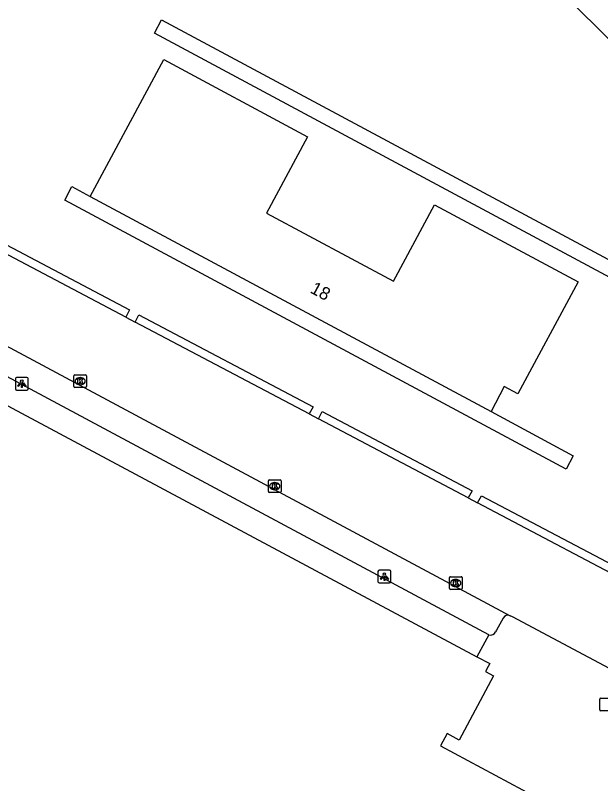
# Model space of a CAD drawing. Extents: x 159489 to 160304, y 383826 to 384530.
# Drawn here: x 160037.7 to 160083.4, y 384048.7 to 384108.8 of the extents above; entities that cross this region are included whole.
import ezdxf

# ---------------------------------------------------------------- set-up
doc = ezdxf.new("R2010")
doc.units = 0
for name, color, linetype in [('IMGEO_Haag', 7, 'Continuous'), ('IMGEO_Kolk', 7, 'Continuous'), ('IMGEO_Lichtpunt', 7, 'Continuous'), ('IMGEO_Muur', 7, 'Continuous'), ('IMGEO_Pand', 7, 'Continuous'), ('IMGEO_Pand_nummerreeks', 7, 'Continuous'), ('IMGEO_Rijbaan_lokaal_open', 7, 'Continuous'), ('IMGEO_Rioolput', 7, 'Continuous'), ('IMGEO_Voetpad_open', 7, 'Continuous')]:
    doc.layers.add(name, color=color, linetype=linetype)

msp = doc.modelspace()

# ---------------------------------------------------------------- linework, layer by layer
at = {"layer": 'IMGEO_Haag'}
for points in [[(160033.002, 384092.187), (160033.287, 384092.784), (160046.606, 384085.746), (160046.301, 384085.17)], [(160047.03, 384084.787), (160047.334, 384085.363), (160060.949, 384078.169), (160060.648, 384077.604)], [(160061.378, 384077.213), (160061.675, 384077.787), (160073.388, 384071.599), (160073.089, 384071.038)], [(160073.826, 384070.649), (160074.121, 384071.211), (160087.845, 384063.961), (160087.565, 384063.401)]]:
    msp.add_lwpolyline(points, dxfattribs=at)
at = {"layer": 'IMGEO_Kolk'}
for p, q in [((160042.238, 384079.744), (160042.238, 384080.596)), ((160042.313, 384080.67), (160043.165, 384080.67)), ((160042.726, 384080.45), (160042.751, 384080.45)), ((160043.239, 384080.596), (160043.239, 384079.744)), ((160043.165, 384079.67), (160042.313, 384079.67)), ((160042.749, 384079.89), (160042.724, 384079.89)), ((160057.457, 384071.53), (160057.457, 384072.382)), ((160057.532, 384072.456), (160058.384, 384072.456)), ((160058.458, 384072.382), (160058.458, 384071.53)), ((160057.945, 384072.236), (160057.97, 384072.236)), ((160058.384, 384071.456), (160057.532, 384071.456)), ((160057.968, 384071.676), (160057.943, 384071.676)), ((160071.614, 384063.944), (160071.614, 384064.796)), ((160071.689, 384064.87), (160072.541, 384064.87)), ((160072.102, 384064.65), (160072.127, 384064.65)), ((160072.615, 384064.796), (160072.615, 384063.944)), ((160072.125, 384064.09), (160072.1, 384064.09)), ((160072.541, 384063.87), (160071.689, 384063.87))]:
    msp.add_line(p, q, dxfattribs=at)
for points in [[(160042.238, 384079.744), (160042.238, 384080.596)], [(160042.313, 384080.67), (160043.165, 384080.67)], [(160042.559, 384080.37), (160042.682, 384080.37), (160042.682, 384080.219), (160042.812, 384080.37), (160042.976, 384080.37), (160042.83, 384080.219), (160042.983, 384079.97), (160042.831, 384079.97), (160042.746, 384080.134), (160042.682, 384080.067), (160042.682, 384079.97), (160042.559, 384079.97), (160042.559, 384080.37)], [(160043.239, 384080.596), (160043.239, 384079.744)], [(160043.165, 384079.67), (160042.313, 384079.67)], [(160057.457, 384071.53), (160057.457, 384072.382)], [(160057.532, 384072.456), (160058.384, 384072.456)], [(160058.458, 384072.382), (160058.458, 384071.53)], [(160057.778, 384072.156), (160057.901, 384072.156), (160057.901, 384072.005), (160058.031, 384072.156), (160058.195, 384072.156), (160058.049, 384072.005), (160058.202, 384071.756), (160058.05, 384071.756), (160057.965, 384071.92), (160057.901, 384071.853), (160057.901, 384071.756), (160057.778, 384071.756), (160057.778, 384072.156)], [(160058.384, 384071.456), (160057.532, 384071.456)], [(160071.614, 384063.944), (160071.614, 384064.796)], [(160071.689, 384064.87), (160072.541, 384064.87)], [(160071.935, 384064.57), (160072.058, 384064.57), (160072.058, 384064.419), (160072.188, 384064.57), (160072.352, 384064.57), (160072.206, 384064.419), (160072.359, 384064.17), (160072.207, 384064.17), (160072.122, 384064.334), (160072.058, 384064.267), (160072.058, 384064.17), (160071.935, 384064.17), (160071.935, 384064.57)], [(160072.615, 384064.796), (160072.615, 384063.944)], [(160072.541, 384063.87), (160071.689, 384063.87)]]:
    msp.add_lwpolyline(points, dxfattribs=at)
for centre, start, end in [((160042.315, 384080.594), 91.55205, 178.44795), ((160042.315, 384080.594), 91.55205, 178.44795), ((160043.163, 384080.594), 1.55205, 88.44795), ((160043.163, 384080.594), 1.55205, 88.44795), ((160042.315, 384079.746), 181.55205, 268.44795), ((160042.315, 384079.746), 181.55205, 268.44795), ((160043.163, 384079.746), 271.55205, 358.44795), ((160043.163, 384079.746), 271.55205, 358.44795), ((160057.534, 384072.38), 91.55205, 178.44795), ((160057.534, 384072.38), 91.55205, 178.44795), ((160058.382, 384072.38), 1.55205, 88.44795), ((160058.382, 384072.38), 1.55205, 88.44795), ((160057.534, 384071.532), 181.55205, 268.44795), ((160057.534, 384071.532), 181.55205, 268.44795), ((160058.382, 384071.532), 271.55205, 358.44795), ((160058.382, 384071.532), 271.55205, 358.44795), ((160071.691, 384064.794), 91.55205, 178.44795), ((160071.691, 384064.794), 91.55205, 178.44795), ((160072.539, 384064.794), 1.55205, 88.44795), ((160072.539, 384064.794), 1.55205, 88.44795), ((160071.691, 384063.946), 181.55205, 268.44795), ((160071.691, 384063.946), 181.55205, 268.44795), ((160072.539, 384063.946), 271.55205, 358.44795), ((160072.539, 384063.946), 271.55205, 358.44795)]:
    msp.add_arc(centre, 0.0765, start, end, dxfattribs=at)
for centre, major_axis, ratio, start_param, end_param in [((160042.725, 384080.17), (-0.387, 0.002), 0.722429, 4.712389, 7.853982), ((160042.75, 384080.17), (-0.39, 0.002), 0.717154, 1.570796, 4.712389), ((160057.944, 384071.956), (-0.387, 0.002), 0.722429, 4.712389, 7.853982), ((160057.969, 384071.956), (-0.39, 0.002), 0.717154, 1.570796, 4.712389), ((160072.101, 384064.37), (-0.387, 0.002), 0.722429, 4.712389, 7.853982), ((160072.126, 384064.37), (-0.39, 0.002), 0.717154, 1.570796, 4.712389)]:
    msp.add_ellipse(centre, major_axis=major_axis, ratio=ratio, start_param=start_param, end_param=end_param, dxfattribs=at)
at = {"layer": 'IMGEO_Lichtpunt'}
for p, q in [((160037.67, 384080.373), (160037.67, 384079.566)), ((160037.67, 384080.373), (160037.67, 384079.566)), ((160038.572, 384080.468), (160037.764, 384080.468)), ((160038.572, 384080.468), (160037.764, 384080.468)), ((160038.666, 384079.566), (160038.666, 384080.373)), ((160038.666, 384079.566), (160038.666, 384080.373)), ((160037.764, 384079.472), (160038.572, 384079.472)), ((160037.764, 384079.472), (160038.572, 384079.472)), ((160066.031, 384065.279), (160066.031, 384064.472)), ((160066.031, 384065.279), (160066.031, 384064.472)), ((160066.933, 384065.374), (160066.125, 384065.374)), ((160066.933, 384065.374), (160066.125, 384065.374)), ((160067.027, 384064.472), (160067.027, 384065.279)), ((160067.027, 384064.472), (160067.027, 384065.279)), ((160066.125, 384064.378), (160066.933, 384064.378)), ((160066.125, 384064.378), (160066.933, 384064.378))]:
    msp.add_line(p, q, dxfattribs=at)
for points in [[(160038.044, 384080.037), (160038.083, 384080.009), (160037.895, 384079.747), (160037.857, 384079.774), (160038.044, 384080.037)], [(160038.146, 384079.989), (160038.193, 384079.989), (160038.193, 384079.667), (160038.146, 384079.667), (160038.146, 384079.989)], [(160038.256, 384080.009), (160038.294, 384080.036), (160038.481, 384079.774), (160038.442, 384079.746), (160038.256, 384080.009)], [(160066.405, 384064.943), (160066.444, 384064.915), (160066.256, 384064.653), (160066.218, 384064.68), (160066.405, 384064.943)], [(160066.507, 384064.895), (160066.554, 384064.895), (160066.554, 384064.573), (160066.507, 384064.573), (160066.507, 384064.895)], [(160066.617, 384064.915), (160066.655, 384064.942), (160066.842, 384064.68), (160066.803, 384064.652), (160066.617, 384064.915)]]:
    msp.add_lwpolyline(points, dxfattribs=at)
for centre in [(160038.169, 384080.171), (160066.53, 384065.077)]:
    msp.add_circle(centre, 0.0994, dxfattribs=at)
for centre, start, end in [((160037.764, 384080.373), 90, 180), ((160037.764, 384080.373), 90, 180), ((160038.572, 384080.373), 0, 90), ((160038.572, 384080.373), 0, 90), ((160037.764, 384079.566), 180, 270), ((160037.764, 384079.566), 180, 270), ((160038.572, 384079.566), 270, 0), ((160038.572, 384079.566), 270, 360), ((160066.125, 384065.279), 90, 180), ((160066.125, 384065.279), 90, 180), ((160066.933, 384065.279), 0, 90), ((160066.933, 384065.279), 0, 90), ((160066.125, 384064.472), 180, 270), ((160066.125, 384064.472), 180, 270), ((160066.933, 384064.472), 270, 0), ((160066.933, 384064.472), 270, 360)]:
    msp.add_arc(centre, 0.0946, start, end, dxfattribs=at)
at = {"layer": 'IMGEO_Muur'}
for points in [[(160048.541, 384107.419), (160049.091, 384108.443), (160088.325, 384087.396), (160087.753, 384086.353), (160048.541, 384107.419)], [(160074.87, 384077.806), (160081.29, 384074.339), (160080.738, 384073.282), (160041.525, 384094.346), (160042.089, 384095.397), (160043.511, 384094.635)]]:
    msp.add_lwpolyline(points, dxfattribs=at)
at = {"layer": 'IMGEO_Pand'}
for points in [[(160043.511, 384094.635), (160049.292, 384105.342), (160060.53, 384099.308), (160057.317, 384093.323), (160067.243, 384087.99), (160070.458, 384093.979), (160081.691, 384087.948), (160076.979, 384079.175), (160075.903, 384079.753), (160074.87, 384077.806)], [(160043.511, 384094.635), (160074.87, 384077.806)], [(160034.428, 384079.656), (160073.755, 384058.611)], [(160073.755, 384058.611), (160074.776, 384058.065), (160074.653, 384057.835), (160074.445, 384057.447), (160075.061, 384057.116), (160072.374, 384052.088), (160071.43, 384052.592), (160070.91, 384051.621), (160077.333, 384048.184), (160084.358, 384044.424), (160120.106, 384025.292)]]:
    msp.add_lwpolyline(points, dxfattribs=at)
at = {"layer": 'IMGEO_Rijbaan_lokaal_open'}
for points in [[(160046.301, 384085.17), (160033.002, 384092.187)], [(160026.914, 384088.319), (160027.802, 384087.843), (160076.371, 384061.813)], [(160046.301, 384085.17), (160047.03, 384084.787)], [(160060.648, 384077.604), (160047.03, 384084.787)], [(160060.648, 384077.604), (160061.378, 384077.213)], [(160073.089, 384071.038), (160061.378, 384077.213)], [(160073.089, 384071.038), (160073.826, 384070.649)], [(160087.565, 384063.401), (160073.826, 384070.649)], [(160171.245, 384010.937), (160125.267, 384035.607), (160090.12, 384054.464), (160085.703, 384056.846), (160076.546, 384061.719), (160076.371, 384061.813)]]:
    msp.add_lwpolyline(points, dxfattribs=at)
at = {"layer": 'IMGEO_Rioolput'}
for p, q in [((160083.368, 384054.443), (160083.368, 384055.295)), ((160083.443, 384055.369), (160084.295, 384055.369)), ((160084.295, 384054.369), (160083.443, 384054.369))]:
    msp.add_line(p, q, dxfattribs=at)
for points in [[(160083.368, 384054.443), (160083.368, 384055.295)], [(160083.443, 384055.369), (160084.295, 384055.369)], [(160084.295, 384054.369), (160083.443, 384054.369)]]:
    msp.add_lwpolyline(points, dxfattribs=at)
for centre, start, end in [((160083.445, 384055.293), 91.55205, 178.44795), ((160083.445, 384055.293), 91.55205, 178.44795), ((160083.445, 384054.445), 181.55205, 268.44795), ((160083.445, 384054.445), 181.55205, 268.44795)]:
    msp.add_arc(centre, 0.0765, start, end, dxfattribs=at)
at = {"layer": 'IMGEO_Voetpad_open'}
for points in [[(160045.909, 384147.6), (160052.358, 384140.503), (160053.933, 384138.772), (160071.087, 384119.92), (160086.321, 384104.707), (160099.143, 384092.122), (160103.841, 384087.441), (160108.884, 384082.468)], [(160074.709, 384060.323), (160027.206, 384085.779), (160026.861, 384085.963), (160026.678, 384086.133)], [(160075.828, 384061.615), (160075.308, 384060.691), (160075.228, 384060.547)], [(160074.709, 384060.323), (160073.755, 384058.611)]]:
    msp.add_lwpolyline(points, dxfattribs=at)
for centre, radius, start, end in [((160076.199, 384061.441), 0.41, 65.23726, 154.83059), ((160074.833, 384060.75), 0.445, 253.86165, 332.82834)]:
    msp.add_arc(centre, radius, start, end, dxfattribs=at)

# ---------------------------------------------------------------- texts
at = {"layer": 'IMGEO_Pand_nummerreeks'}
msp.add_text('18', height=1, rotation=331.78183, dxfattribs=at).set_placement((160060.654, 384087.137))

doc.saveas('drawing.dxf')
